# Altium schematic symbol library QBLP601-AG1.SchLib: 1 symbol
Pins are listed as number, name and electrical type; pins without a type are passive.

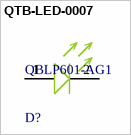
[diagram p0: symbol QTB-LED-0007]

## QTB-LED-0007
designator D?, comment QBLP601-AG1
LED YELLOW/GREEN CLEAR 0603 SMD; Manufacturer: QT Brightek (QTB); Lens Size: 0.8mm; Luminous Intensity: 45mcd; Test Current: 20mA; Lens Color: Colorless; Lens Style: Flat; Forward Voltage: 2.0V; Wavelength - Dominant: 570nm
footprint QBLP601-AG1-MFG
pins: 1 ANODE (+), 2 CATHODE (-)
